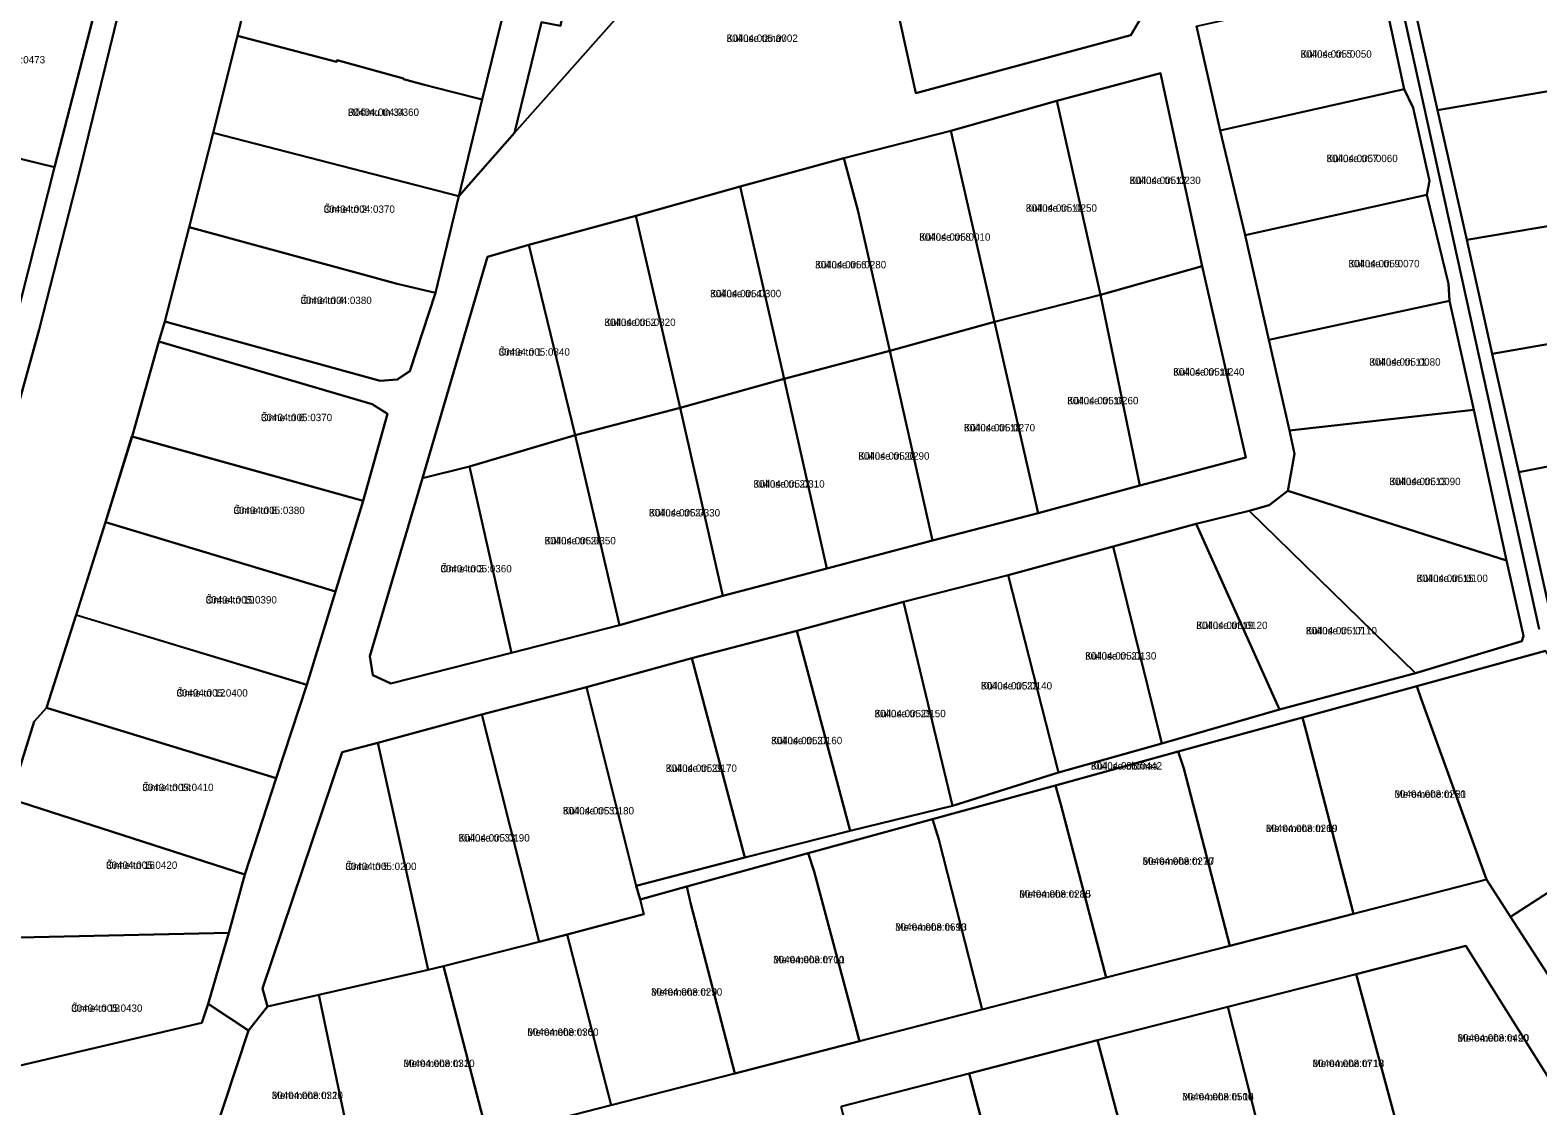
# Model space of a CAD drawing. Extents: x 542681 to 554572, y 6566489 to 6580482.
# Drawn here: x 543956.1 to 544263.2, y 6576896.6 to 6577115.7 of the extents above; entities that cross this region are included whole.
import ezdxf

# ---------------------------------------------------------------- set-up
doc = ezdxf.new("R2010")
doc.units = 0
for name, color, linetype in [('L_AADRESS', 7, 'Continuous'), ('PIIR', 7, 'Continuous'), ('TUNNUS', 7, 'Continuous')]:
    doc.layers.add(name, color=color, linetype=linetype)

msp = doc.modelspace()

# ---------------------------------------------------------------- linework, layer by layer
at = {"layer": 'PIIR'}
for points in [[(543807.92, 6576662.98), (543904.97, 6576885.47), (543907.57, 6576895.31), (543910.99, 6576906.44), (543922.56, 6576941.94), (543936.45, 6576984.61), (543948.61, 6577021.3), (543957.88, 6577054.74), (543966.17, 6577087.14), (543974.03, 6577119.2), (543981.47, 6577151), (543988.44, 6577183.28), (543996.05, 6577221.97), (544002.64, 6577259.57), (544005.96, 6577279.79), (544014.14, 6577348.31), (544016.62, 6577369.15), (544023.92, 6577429.37), (544023.1, 6577434.48), (544025.4, 6577449.01), (544027.21, 6577460.39), (544030.15, 6577550.17)], [(543952.91, 6577055.9), (543961.04, 6577087.76), (543969.28, 6577119.84), (543973.68, 6577136.98), (543976.6, 6577151.88), (543983, 6577184.45), (543990.52, 6577222.87), (543997.84, 6577259.95), (544004.56, 6577302.46), (544005.14, 6577308.18), (544009.28, 6577348.44), (544014.14, 6577348.31), (544005.96, 6577279.79), (544002.64, 6577259.57), (543996.05, 6577221.97), (543988.44, 6577183.28), (543981.47, 6577151), (543974.03, 6577119.2), (543966.17, 6577087.14), (543957.88, 6577054.74), (543948.61, 6577021.3)], [(544088.25, 6577270.53), (544083.69, 6577241.1), (544080.02, 6577216.88), (544079.79, 6577215.37), (544072.96, 6577175.07), (544061.83, 6577124.3), (544065.5, 6577123.55), (544064.08, 6577116.57), (544060.25, 6577117.34), (544054.74, 6577094.79), (544043.36, 6577081.91), (544048.15, 6577101.6), (544053.03, 6577121.49), (544057.31, 6577141.01), (544061.68, 6577160.97), (544065.91, 6577181.35), (544069.36, 6577201.67), (544072.86, 6577221.8), (544075.94, 6577242.44), (544079.61, 6577266.72)], [(544026.68, 6577265.1), (544024.78, 6577250.04), (544020.16, 6577230.32), (544017.69, 6577211.17), (544014.34, 6577191.11), (544011.89, 6577172.09), (544007.52, 6577152.78), (544002.68, 6577132.74), (543998.32, 6577114.57), (543993.36, 6577094.76), (543988.42, 6577075.56), (543983.52, 6577056.39), (543982.26, 6577052.27), (543976.84, 6577032.94), (543971.38, 6577015.47), (543965.45, 6576996.6), (543959.41, 6576977.68), (543956.86, 6576974.93), (543952, 6576959.13)], [(544193.67, 6577116.5), (544198.52, 6577095.28), (544203.56, 6577073.95), (544208.41, 6577052.65), (544212.62, 6577034.19), (544213.63, 6577029.4), (544212.25, 6577021.85), (544208.49, 6577018.93), (544204.4, 6577017.79), (544193.59, 6577015.16), (544176.7, 6577010.54), (544155.34, 6577004.72), (544133.96, 6576999.26), (544112.22, 6576993.38), (544090.89, 6576987.77), (544069.41, 6576981.92), (544048.08, 6576976.32), (544026.88, 6576970.53), (544019.61, 6576968.67), (544003.4, 6576920.52), (544004.39, 6576916.85), (544000.54, 6576911.95), (543992.29, 6576917.41), (543996.56, 6576931.85), (543999.81, 6576943.77), (544006.19, 6576963.36), (544012.41, 6576982.4), (544018.25, 6577001.4), (544023.92, 6577019.87), (544028.86, 6577037.54), (544025.74, 6577039.54), (543982.26, 6577052.27), (543983.52, 6577056.39), (544027.38, 6577044.28), (544030.81, 6577044.54), (544033.42, 6577046.25), (544038.64, 6577062.23), (544043.36, 6577081.91), (544054.74, 6577094.79), (544121.6, 6577170.23)], [(544126.55, 6577147.86), (544136.48, 6577102.88), (544180.29, 6577114.66), (544183.2, 6577119.62)], [(544263.5, 6576993.69), (544232.86, 6577132.75), (544230.87, 6577140.38), (544234.67, 6577140.84), (544238.7, 6577141.31), (544236.96, 6577125.44), (544242.8, 6577099.39), (544248.72, 6577072.99), (544253.92, 6577049.8), (544259.33, 6577025.66), (544266.36, 6576994.23)], [(544232.86, 6577132.75), (544263.5, 6576993.69)], [(544264.77, 6576989.29), (544238.54, 6576982.1), (544215.28, 6576975.72), (544189.97, 6576968.78), (544164.94, 6576961.89), (544139.92, 6576955.03), (544114.54, 6576948.06), (544089.82, 6576941.28), (544080.31, 6576938.68), (544079.54, 6576941.42), (544101.67, 6576947.19), (544123.1, 6576952.67), (544143.94, 6576957.76), (544165.53, 6576964.52), (544186.64, 6576970.42), (544210.58, 6576977.32), (544238.28, 6576984.78), (544259.95, 6576991.25), (544260.28, 6576992.32), (544256.81, 6577007.72), (544250.18, 6577038.36), (544245.25, 6577060.54), (544245.02, 6577064.03), (544240.6, 6577082.18), (544241.16, 6577084.98), (544237.81, 6577099.88), (544236, 6577103.69), (544231.41, 6577124.89)], [(544083.14, 6576706.63), (544069.43, 6576728.43), (544055.16, 6576751.13), (544041.07, 6576773.52), (544012.45, 6576754.96), (544009.2, 6576760.05), (544037.62, 6576778.58), (544022.31, 6576800.71), (544007.03, 6576823.11), (543982.8, 6576859.17), (543988.16, 6576874.59), (544022.38, 6576883.4), (544049.33, 6576890.31), (544074.45, 6576896.76), (544099.65, 6576903.25), (544125.05, 6576909.8), (544150.03, 6576916.24), (544175.24, 6576922.74), (544200.45, 6576929.24), (544225.66, 6576935.73), (544252.75, 6576942.7), (544257.68, 6576935.15), (544271.85, 6576913.23)], [(544267.52, 6576899.03), (544248.56, 6576929.2), (544226.19, 6576923.47), (544200.03, 6576916.78), (544173.51, 6576909.99), (544147.38, 6576903.24), (544121.31, 6576896.51)]]:
    msp.add_lwpolyline(points, dxfattribs=at)
for points in [[(544079.79, 6577215.37), (544126.52, 6577216.45), (544121.6, 6577170.23), (544054.74, 6577094.79), (544060.25, 6577117.34), (544064.08, 6577116.57), (544065.5, 6577123.55), (544061.83, 6577124.3), (544072.96, 6577175.07)], [(544136.18, 6577149.35), (544141.07, 6577127.85), (544179.44, 6577137.12), (544183.2, 6577119.62), (544180.29, 6577114.66), (544136.48, 6577102.88), (544126.55, 6577147.86)], [(544018.49, 6577109.27), (543998.32, 6577114.57), (544002.68, 6577132.74), (544053.03, 6577121.49), (544048.15, 6577101.6), (544041.99, 6577103.14), (544036.13, 6577104.63), (544032.11, 6577105.69), (544032.15, 6577105.84), (544018.58, 6577109.61)], [(544236.96, 6577125.44), (544286.02, 6577133.9), (544292.53, 6577118.03), (544285.26, 6577113.83), (544278.03, 6577105.45), (544242.8, 6577099.39)], [(543920.13, 6577097.75), (543927.62, 6577130.07), (543969.28, 6577119.84), (543961.04, 6577087.76)], [(544193.67, 6577116.5), (544231.41, 6577124.89), (544236, 6577103.69), (544198.52, 6577095.28)], [(543998.32, 6577114.57), (544018.49, 6577109.27), (544018.58, 6577109.61), (544032.15, 6577105.84), (544032.11, 6577105.69), (544036.13, 6577104.63), (544041.99, 6577103.14), (544048.15, 6577101.6), (544043.36, 6577081.91), (543993.36, 6577094.76)], [(544194.83, 6577067.6), (544186.34, 6577106.96), (544165.25, 6577101.31), (544143.64, 6577095.22), (544121.84, 6577089.63), (544100.73, 6577083.86), (544079.46, 6577077.88), (544057.64, 6577072), (544049.23, 6577069.55), (544035.96, 6577024.46), (544025.23, 6576988.23), (544025.87, 6576984.32), (544029.56, 6576982.62), (544054.1, 6576988.86), (544076.15, 6576994.5), (544097.17, 6577000.47), (544118.37, 6577006.07), (544139.86, 6577011.74), (544161.39, 6577017.34), (544182.14, 6577022.98), (544203.73, 6577028.67)], [(544165.25, 6577101.31), (544186.34, 6577106.96), (544194.83, 6577067.6), (544174.14, 6577061.78)], [(544242.8, 6577099.39), (544278.03, 6577105.45), (544281.62, 6577104.36), (544292.35, 6577104.8), (544296.14, 6577080.98), (544248.72, 6577072.99)], [(544198.52, 6577095.28), (544236, 6577103.69), (544237.81, 6577099.88), (544241.16, 6577084.98), (544240.6, 6577082.18), (544203.56, 6577073.95)], [(544143.64, 6577095.22), (544165.25, 6577101.31), (544174.14, 6577061.78), (544152.53, 6577056.3)], [(543912.32, 6577065.86), (543920.13, 6577097.75), (543961.04, 6577087.76), (543952.91, 6577055.9)], [(543993.36, 6577094.76), (544043.36, 6577081.91), (544038.64, 6577062.23), (544030.8, 6577064.01), (544022.16, 6577066.38), (543988.42, 6577075.56)], [(544152.53, 6577056.3), (544131.19, 6577050.39), (544124.7, 6577079.06), (544121.84, 6577089.63), (544143.64, 6577095.22)], [(544100.73, 6577083.86), (544121.84, 6577089.63), (544124.7, 6577079.06), (544131.19, 6577050.39), (544109.69, 6577044.71)], [(544079.46, 6577077.88), (544100.73, 6577083.86), (544109.69, 6577044.71), (544088.46, 6577038.79)], [(544203.56, 6577073.95), (544240.6, 6577082.18), (544245.02, 6577064.03), (544245.25, 6577060.54), (544208.41, 6577052.65)], [(544248.72, 6577072.99), (544296.14, 6577080.98), (544299.89, 6577057.8), (544253.92, 6577049.8)], [(544057.64, 6577072), (544079.46, 6577077.88), (544088.46, 6577038.79), (544067.06, 6577033.21)], [(543988.42, 6577075.56), (544022.16, 6577066.38), (544030.8, 6577064.01), (544038.64, 6577062.23), (544033.42, 6577046.25), (544030.81, 6577044.54), (544027.38, 6577044.28), (543983.52, 6577056.39)], [(544035.96, 6577024.46), (544049.23, 6577069.55), (544057.64, 6577072), (544067.06, 6577033.21), (544045.59, 6577026.85)], [(544194.83, 6577067.6), (544203.73, 6577028.67), (544182.14, 6577022.98), (544174.14, 6577061.78)], [(544174.14, 6577061.78), (544182.14, 6577022.98), (544161.39, 6577017.34), (544152.53, 6577056.3)], [(544208.41, 6577052.65), (544245.25, 6577060.54), (544250.18, 6577038.36), (544212.62, 6577034.19)], [(544152.53, 6577056.3), (544161.39, 6577017.34), (544139.86, 6577011.74), (544131.19, 6577050.39)], [(544253.92, 6577049.8), (544299.89, 6577057.8), (544303.68, 6577034.31), (544259.33, 6577025.66)], [(543982.26, 6577052.27), (544025.74, 6577039.54), (544028.86, 6577037.54), (544023.92, 6577019.87), (543976.84, 6577032.94)], [(544131.19, 6577050.39), (544139.86, 6577011.74), (544118.37, 6577006.07), (544109.69, 6577044.71)], [(544109.69, 6577044.71), (544118.37, 6577006.07), (544097.17, 6577000.47), (544088.46, 6577038.79)], [(544097.17, 6577000.47), (544076.15, 6576994.5), (544067.06, 6577033.21), (544088.46, 6577038.79)], [(544213.63, 6577029.4), (544212.62, 6577034.19), (544250.18, 6577038.36), (544256.81, 6577007.72), (544212.25, 6577021.85)], [(544259.33, 6577025.66), (544303.68, 6577034.31), (544307.82, 6577014.16), (544266.36, 6576994.23)], [(543976.79, 6577032.93), (544023.92, 6577019.87), (544018.25, 6577001.4), (543971.38, 6577015.47)], [(544067.06, 6577033.21), (544076.15, 6576994.5), (544054.1, 6576988.86), (544045.59, 6577026.85)], [(544025.87, 6576984.32), (544025.23, 6576988.23), (544035.96, 6577024.46), (544045.59, 6577026.85), (544054.1, 6576988.86), (544029.56, 6576982.62)], [(544208.49, 6577018.93), (544212.25, 6577021.85), (544256.81, 6577007.72), (544260.28, 6576992.32), (544259.95, 6576991.25), (544238.28, 6576984.78), (544204.4, 6577017.79)], [(544193.59, 6577015.16), (544204.4, 6577017.79), (544238.28, 6576984.78), (544210.58, 6576977.32)], [(543971.38, 6577015.47), (544018.25, 6577001.4), (544012.41, 6576982.4), (543965.4, 6576996.59)], [(544176.7, 6577010.54), (544193.59, 6577015.16), (544210.58, 6576977.32), (544186.64, 6576970.42)], [(544155.34, 6577004.72), (544176.7, 6577010.54), (544186.64, 6576970.42), (544165.53, 6576964.52)], [(544133.96, 6576999.26), (544155.34, 6577004.72), (544165.53, 6576964.52), (544143.94, 6576957.76)], [(544112.22, 6576993.38), (544133.96, 6576999.26), (544143.94, 6576957.76), (544123.1, 6576952.67)], [(543965.45, 6576996.6), (544012.41, 6576982.4), (544006.19, 6576963.36), (543959.41, 6576977.68)], [(544090.89, 6576987.77), (544112.22, 6576993.38), (544123.1, 6576952.67), (544101.67, 6576947.19)], [(544252.75, 6576942.7), (544239.47, 6576979.52), (544238.54, 6576982.1), (544264.77, 6576989.29), (544287.78, 6576954.61), (544284.32, 6576952.37), (544257.68, 6576935.15)], [(544069.41, 6576981.92), (544090.89, 6576987.77), (544101.67, 6576947.19), (544079.54, 6576941.42)], [(544048.08, 6576976.32), (544069.41, 6576981.92), (544079.54, 6576941.42), (544080.31, 6576938.68), (544081.08, 6576935.64), (544065.46, 6576931.54), (544059.77, 6576930.04)], [(544216.06, 6576972.65), (544215.28, 6576975.72), (544238.54, 6576982.1), (544239.47, 6576979.52), (544252.75, 6576942.7), (544225.66, 6576935.73)], [(543956.86, 6576974.93), (543959.41, 6576977.68), (544006.19, 6576963.36), (543999.81, 6576943.77), (543952, 6576959.13)], [(544037.14, 6576924.33), (544026.88, 6576970.53), (544048.08, 6576976.32), (544059.77, 6576930.04), (544040.24, 6576925.11)], [(544191.07, 6576965.31), (544189.97, 6576968.78), (544215.28, 6576975.72), (544216.06, 6576972.65), (544225.66, 6576935.73), (544200.45, 6576929.24)], [(544004.39, 6576916.85), (544003.4, 6576920.52), (544019.61, 6576968.67), (544026.88, 6576970.53), (544037.14, 6576924.33), (544014.9, 6576919.26)], [(544166.06, 6576957.98), (544164.94, 6576961.89), (544189.97, 6576968.78), (544191.07, 6576965.31), (544200.45, 6576929.24), (544175.24, 6576922.74)], [(544141.18, 6576950.86), (544139.92, 6576955.03), (544164.94, 6576961.89), (544166.06, 6576957.98), (544175.24, 6576922.74), (544150.03, 6576916.24)], [(543952, 6576959.13), (543999.81, 6576943.77), (543996.56, 6576931.85), (543941.5, 6576930.66)], [(544115.75, 6576944.37), (544114.54, 6576948.06), (544139.92, 6576955.03), (544141.18, 6576950.86), (544150.03, 6576916.24), (544125.05, 6576909.8)], [(544257.68, 6576935.15), (544284.32, 6576952.37), (544287.78, 6576954.61), (544302.13, 6576932.97), (544298.54, 6576930.63), (544271.85, 6576913.23)], [(544090.61, 6576937.95), (544089.82, 6576941.28), (544114.54, 6576948.06), (544115.75, 6576944.37), (544125.05, 6576909.8), (544099.65, 6576903.25)], [(544065.46, 6576931.54), (544081.08, 6576935.64), (544080.31, 6576938.68), (544089.82, 6576941.28), (544090.61, 6576937.95), (544099.65, 6576903.25), (544074.45, 6576896.76)], [(543932.34, 6576899.7), (543941.5, 6576930.66), (543996.56, 6576931.85), (543992.29, 6576917.41), (543991.03, 6576913.55), (543945.88, 6576902.92)], [(544040.24, 6576925.11), (544059.77, 6576930.04), (544065.46, 6576931.54), (544074.45, 6576896.76), (544049.33, 6576890.31)], [(544236.42, 6576892.73), (544234.62, 6576892.27), (544226.19, 6576923.47), (544248.56, 6576929.2), (544267.52, 6576899.03), (544267.28, 6576894.17), (544255.76, 6576884.03), (544251.02, 6576892.37), (544240.1, 6576887.96)], [(544014.9, 6576919.26), (544037.14, 6576924.33), (544040.24, 6576925.11), (544049.33, 6576890.31), (544022.38, 6576883.4)], [(544200.03, 6576916.78), (544226.19, 6576923.47), (544234.62, 6576892.27), (544208.01, 6576885.48)], [(543929.19, 6576883.52), (543932.34, 6576899.7), (543945.88, 6576902.92), (543991.03, 6576913.55), (543992.29, 6576917.41), (544000.54, 6576911.95), (543988.16, 6576874.59), (543982.8, 6576859.17)], [(544000.54, 6576911.95), (544004.39, 6576916.85), (544014.9, 6576919.26), (544022.38, 6576883.4), (543988.16, 6576874.59)], [(544173.51, 6576909.99), (544200.03, 6576916.78), (544208.01, 6576885.48), (544202.49, 6576884.08), (544181.8, 6576878.81)], [(544147.38, 6576903.24), (544173.51, 6576909.99), (544181.8, 6576878.81), (544178.89, 6576878.07), (544155.59, 6576872.18)], [(544121.31, 6576896.51), (544147.38, 6576903.24), (544155.59, 6576872.18), (544147.11, 6576870.03), (544129.37, 6576865.54)]]:
    msp.add_lwpolyline(points, close=True, dxfattribs=at)

# ---------------------------------------------------------------- texts
at = {"layer": 'L_AADRESS'}
for s, p in [('Külluse tänav', (544097.95, 6577113.31)), ('Külluse tn 5', (544214.88, 6577110.09)), ('Rõõmu tn 34', (544020.78, 6577098.24)), ('Külluse tn 7', (544220.17, 6577088.82)), ('Külluse tn 12', (544180.04, 6577084.36)), ('Õnne tn 2', (544015.86, 6577078.5)), ('Külluse tn 10', (544158.89, 6577078.72)), ('Külluse tn 8', (544137.19, 6577072.81)), ('Külluse tn 6', (544115.96, 6577067.19)), ('Külluse tn 9', (544224.62, 6577067.41)), ('Õnne tn 4', (544011.15, 6577059.92)), ('Külluse tn 4', (544094.57, 6577061.31)), ('Külluse tn 2', (544073.05, 6577055.46)), ('Õnne tn 1', (544051.51, 6577049.41)), ('Külluse tn 14', (544188.93, 6577045.36)), ('Külluse tn 11', (544228.9, 6577047.37)), ('Külluse tn 16', (544167.34, 6577039.51)), ('Õnne tn 6', (544003.08, 6577036.07)), ('Külluse tn 18', (544146.29, 6577033.99)), ('Külluse tn 20', (544124.77, 6577028.23)), ('Külluse tn 22', (544103.41, 6577022.54)), ('Külluse tn 13', (544232.98, 6577023.04)), ('Õnne tn 8', (543997.5, 6577017.16)), ('Külluse tn 24', (544082.12, 6577016.66)), ('Külluse tn 26', (544060.87, 6577010.98)), ('Õnne tn 3', (544039.66, 6577005.28)), ('Külluse tn 15', (544238.53, 6577003.32)), ('Õnne tn 10', (543991.82, 6576998.93)), ('Külluse tn 19', (544193.64, 6576993.74)), ('Külluse tn 17', (544215.94, 6576992.66)), ('Külluse tn 21', (544170.99, 6576987.52)), ('Õnne tn 12', (543985.88, 6576979.98)), ('Külluse tn 23', (544149.75, 6576981.43)), ('Külluse tn 25', (544128.08, 6576975.78)), ('Külluse tn 27', (544107, 6576970.28)), ('Külluse üldmaa', (544172.16, 6576965.12)), ('Külluse tn 29', (544085.54, 6576964.65)), ('Õnne tn 14', (543978.91, 6576960.73)), ('Meremehe tn 21', (544234.02, 6576959.37)), ('Külluse tn 31', (544064.58, 6576955.98)), ('Külluse tn 33', (544043.33, 6576950.46)), ('Meremehe tn 19', (544207.81, 6576952.4)), ('Õnne tn 16', (543971.53, 6576944.9)), ('Õnne tn 5', (544020.27, 6576944.66)), ('Meremehe tn 17', (544182.7, 6576945.72)), ('Meremehe tn 15', (544157.58, 6576939.03)), ('Meremehe tn 13', (544132.29, 6576932.3)), ('Meremehe tn 11', (544107.43, 6576925.68)), ('Meremehe tn 9', (544082.55, 6576919.07)), ('Õnne tn 18', (543964.43, 6576915.78)), ('Meremehe tn 5', (544057.35, 6576910.9)), ('Meremehe tn 20', (544246.86, 6576909.73)), ('Meremehe tn 3', (544032.11, 6576904.54)), ('Meremehe tn 18', (544217.32, 6576904.53)), ('Meremehe tn 1', (544005.27, 6576898.02)), ('Meremehe tn 16', (544190.76, 6576897.75))]:
    msp.add_text(s, height=1.5, dxfattribs=at).set_placement(p)
at = {"layer": 'TUNNUS'}
for s, p in [('30404:005:0002', (544097.95, 6577113.31)), ('30404:005:0050', (544214.88, 6577110.09)), ('30501:001:0473', (543944.6, 6577108.92)), ('30404:004:0360', (544020.78, 6577098.24)), ('30404:005:0060', (544220.17, 6577088.82)), ('30404:005:0230', (544180.04, 6577084.36)), ('30404:005:0250', (544158.89, 6577078.72)), ('30404:004:0370', (544015.86, 6577078.5)), ('30404:005:0010', (544137.19, 6577072.81)), ('30404:005:0280', (544115.96, 6577067.19)), ('30404:005:0070', (544224.62, 6577067.41)), ('30404:005:0300', (544094.57, 6577061.31)), ('30404:004:0380', (544011.15, 6577059.92)), ('30404:005:0320', (544073.05, 6577055.46)), ('30404:005:0340', (544051.51, 6577049.41)), ('30404:005:0240', (544188.93, 6577045.36)), ('30404:005:0080', (544228.9, 6577047.37)), ('30404:005:0260', (544167.34, 6577039.51)), ('30404:005:0370', (544003.08, 6577036.07)), ('30404:005:0270', (544146.29, 6577033.99)), ('30404:005:0290', (544124.77, 6577028.23)), ('30404:005:0310', (544103.41, 6577022.54)), ('30404:005:0090', (544232.98, 6577023.04)), ('30404:005:0380', (543997.5, 6577017.16)), ('30404:005:0330', (544082.12, 6577016.66)), ('30404:005:0350', (544060.87, 6577010.98)), ('30404:005:0360', (544039.66, 6577005.28)), ('30404:005:0100', (544238.53, 6577003.32)), ('30404:005:0390', (543991.82, 6576998.93)), ('30404:005:0120', (544193.64, 6576993.74)), ('30404:005:0110', (544215.94, 6576992.66)), ('30404:005:0130', (544170.99, 6576987.52)), ('30404:005:0140', (544149.75, 6576981.43)), ('30404:005:0400', (543985.88, 6576979.98)), ('30404:005:0150', (544128.08, 6576975.78)), ('30404:005:0160', (544107, 6576970.28)), ('30404:005:0442', (544172.16, 6576965.12)), ('30404:005:0170', (544085.54, 6576964.65)), ('30404:005:0410', (543978.91, 6576960.73)), ('30404:008:0250', (544234.02, 6576959.37)), ('30404:005:0180', (544064.58, 6576955.98)), ('30404:005:0190', (544043.33, 6576950.46)), ('30404:008:0260', (544207.81, 6576952.4)), ('30404:005:0420', (543971.53, 6576944.9)), ('30404:005:0200', (544020.27, 6576944.66)), ('30404:008:0270', (544182.7, 6576945.72)), ('30404:008:0280', (544157.58, 6576939.03)), ('30404:008:0690', (544132.29, 6576932.3)), ('30404:008:0700', (544107.43, 6576925.68)), ('30404:008:0290', (544082.55, 6576919.07)), ('30404:005:0430', (543964.43, 6576915.78)), ('30404:008:0300', (544057.35, 6576910.9)), ('30404:008:0490', (544246.86, 6576909.73)), ('30404:008:0310', (544032.11, 6576904.54)), ('30404:008:0710', (544217.32, 6576904.53)), ('30404:008:0320', (544005.27, 6576898.02)), ('30404:008:0500', (544190.76, 6576897.75))]:
    msp.add_text(s, height=1.5, dxfattribs=at).set_placement(p)

doc.saveas('drawing.dxf')
